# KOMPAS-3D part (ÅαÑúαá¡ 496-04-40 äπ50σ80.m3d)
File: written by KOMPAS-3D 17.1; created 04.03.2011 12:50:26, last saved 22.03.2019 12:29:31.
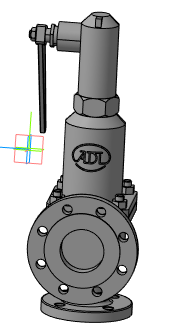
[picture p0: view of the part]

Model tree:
1. Операция без истории:1

Referenced files in C:\Users\tra\Desktop\Детали с марк. для Сферы\bsv\Desktop\Si 57\: VIC_496_50x80_3d.a3d
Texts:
  Viktor2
